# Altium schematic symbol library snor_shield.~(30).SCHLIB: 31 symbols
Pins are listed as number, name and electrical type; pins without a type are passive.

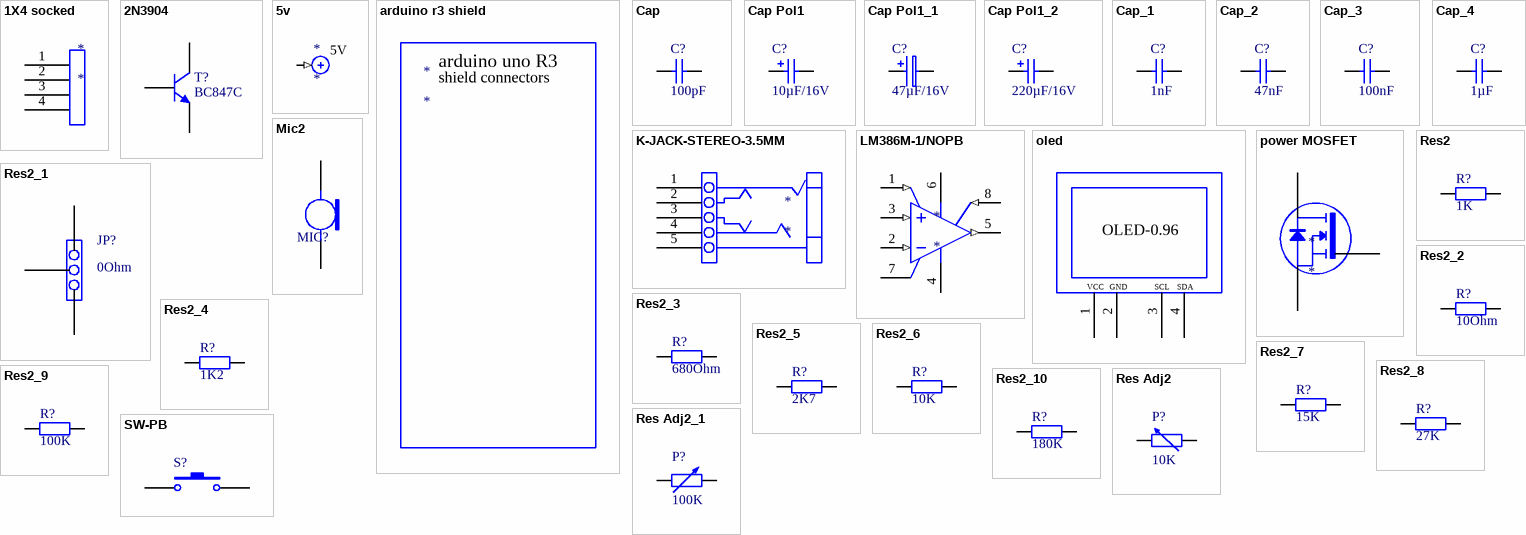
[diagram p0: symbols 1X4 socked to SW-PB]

## 1X4 socked
designator *
pins: 1 9, 2 10, 3 11, 4 12

## 2N3904
designator T?, comment BC847C
NPN General Purpose Amplifier
footprint bipolar BjT
simulation model 2N3904 (NPN)
signal-integrity model 2N3904
pins: 1 E, 2 B, 3 C

## 5v
designator *
pins: 1 (in)

## arduino r3 shield
designator *

## Cap
designator C?  value 100pF  (hidden comment: Cap)
Capacitor
footprint RAD-0.3 (Radial Cap, Thru-Hole; 2 Leads; 0.3 in Pin Spacing)
simulation model CAP (Capacitor)
signal-integrity model Cap
pins: 1, 2

## Cap Pol1
designator C?  value 10µF/16V  (hidden comment: Cap Pol1)
Polarized Capacitor (Radial)
simulation model CAP (Capacitor)
signal-integrity model Cap Pol
pins: 1, 2
1 alternate drawing of the same symbol

## Cap Pol1_1
designator C?, comment value 47µF/16V  (hidden comment: Cap Pol1)
Polarized Capacitor (Radial)
footprint RB7.6-15 (Polarized Capacitor (Radial); 2 Leads)
simulation model CAP (Capacitor)
signal-integrity model Cap Pol
pins: 1, 2
1 alternate drawing of the same symbol

## Cap Pol1_2
designator C?, comment value 220µF/16V  (hidden comment: Cap Pol1)
Polarized Capacitor (Radial)
footprint RB7.6-15 (Polarized Capacitor (Radial); 2 Leads)
simulation model CAP (Capacitor)
signal-integrity model Cap Pol
pins: 1, 2
1 alternate drawing of the same symbol

## Cap_1
designator C?, comment value 1nF  (hidden comment: Cap)
Capacitor
footprint RAD-0.3 (Radial Cap, Thru-Hole; 2 Leads; 0.3 in Pin Spacing)
simulation model CAP (Capacitor)
signal-integrity model Cap
pins: 1, 2

## Cap_2
designator C?, comment value 47nF  (hidden comment: Cap)
Capacitor
footprint RAD-0.3 (Radial Cap, Thru-Hole; 2 Leads; 0.3 in Pin Spacing)
simulation model CAP (Capacitor)
signal-integrity model Cap
pins: 1, 2

## Cap_3
designator C?, comment value 100nF  (hidden comment: Cap)
Capacitor
footprint RAD-0.3 (Radial Cap, Thru-Hole; 2 Leads; 0.3 in Pin Spacing)
simulation model CAP (Capacitor)
signal-integrity model Cap
pins: 1, 2

## Cap_4
designator C?, comment value 1µF  (hidden comment: Cap)
Capacitor
footprint RAD-0.3 (Radial Cap, Thru-Hole; 2 Leads; 0.3 in Pin Spacing)
simulation model CAP (Capacitor)
signal-integrity model Cap
pins: 1, 2

## K-JACK-STEREO-3.5MM
designator *
footprint adioplug3.5mm
pins: 1, 2, 3, 4, 5

## LM386M-1/NOPB
designator *
footprint LM386M-1/NOPB
pins: 1 GAIN (in), 2 IN- (in), 3 IN+ (in), 4 GND (power), 5 VOUT (out), 6 VS (power), 7 BYPASS, 8 GAIN (in)

## Mic2
designator MIC?  (value not drawn)
Microphone
footprint Electret Condenser Microphone
pins: 1, 2

## oled
designator ?
footprint oled scherm
pins: 1 VCC, 2 GND, 3 SCL, 4 SDA

## power MOSFET
designator *
footprint power mosfet
pins: 6, 7, 8

## Res2
designator R?  value 1K  (hidden comment: Res2)
Resistor
simulation model RESISTOR (Resistor)
signal-integrity model Res
footprint SMD 0805
pins: 1, 2

## Res2_1
designator JP?, comment value 0Ohm  (hidden comment: Res2)
Resistor
simulation model RESISTOR (Resistor)
signal-integrity model Res
footprint SMD 0805
pins: 14, 15, 17

## Res2_2
designator R?, comment value 10Ohm  (hidden comment: Res2)
Resistor
simulation model RESISTOR (Resistor)
signal-integrity model Res
footprint SMD 0805
pins: 1, 2

## Res2_3
designator R?, comment value 680Ohm  (hidden comment: Res2)
Resistor
simulation model RESISTOR (Resistor)
signal-integrity model Res
footprint SMD 0805
pins: 1, 2

## Res2_4
designator R?, comment value 1K2  (hidden comment: Res2)
Resistor
simulation model RESISTOR (Resistor)
signal-integrity model Res
footprint SMD 0805
pins: 1, 2

## Res2_5
designator R?, comment value 2K7  (hidden comment: Res2)
Resistor
simulation model RESISTOR (Resistor)
signal-integrity model Res
footprint SMD 0805
pins: 1, 2

## Res2_6
designator R?, comment value 10K  (hidden comment: Res2)
Resistor
simulation model RESISTOR (Resistor)
signal-integrity model Res
footprint SMD 0805
pins: 1, 2

## Res2_7
designator R?, comment value 15K  (hidden comment: Res2)
Resistor
simulation model RESISTOR (Resistor)
signal-integrity model Res
footprint SMD 0805
pins: 1, 2

## Res2_8
designator R?, comment value 27K  (hidden comment: Res2)
Resistor
simulation model RESISTOR (Resistor)
signal-integrity model Res
footprint SMD 0805
pins: 1, 2

## Res2_9
designator R?, comment value 100K  (hidden comment: Res2)
Resistor
simulation model RESISTOR (Resistor)
signal-integrity model Res
footprint SMD 0805
pins: 1, 2

## Res2_10
designator R?, comment value 180K  (hidden comment: Res2)
Resistor
simulation model RESISTOR (Resistor)
signal-integrity model Res
footprint SMD 0805
pins: 1, 2

## Res Adj2
designator P?  value 10K  (hidden comment: Res Adj2)
Variable Resistor; Set Position: 0.5
simulation model VRES (Variable Resistor)
signal-integrity model Res Adj
footprint potmeter
pins: 1, 2, 3

## Res Adj2_1
designator P?, comment value 100K  (hidden comment: Res Adj2)
Variable Resistor; Set Position: 0.5
simulation model VRES (Variable Resistor)
signal-integrity model Res Adj
footprint potmeter
pins: 1, 2, 3

## SW-PB
designator S?  (value not drawn)
Switch
footprint SPST-2 (Switch; 2 Leads)
pins: 1, 2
